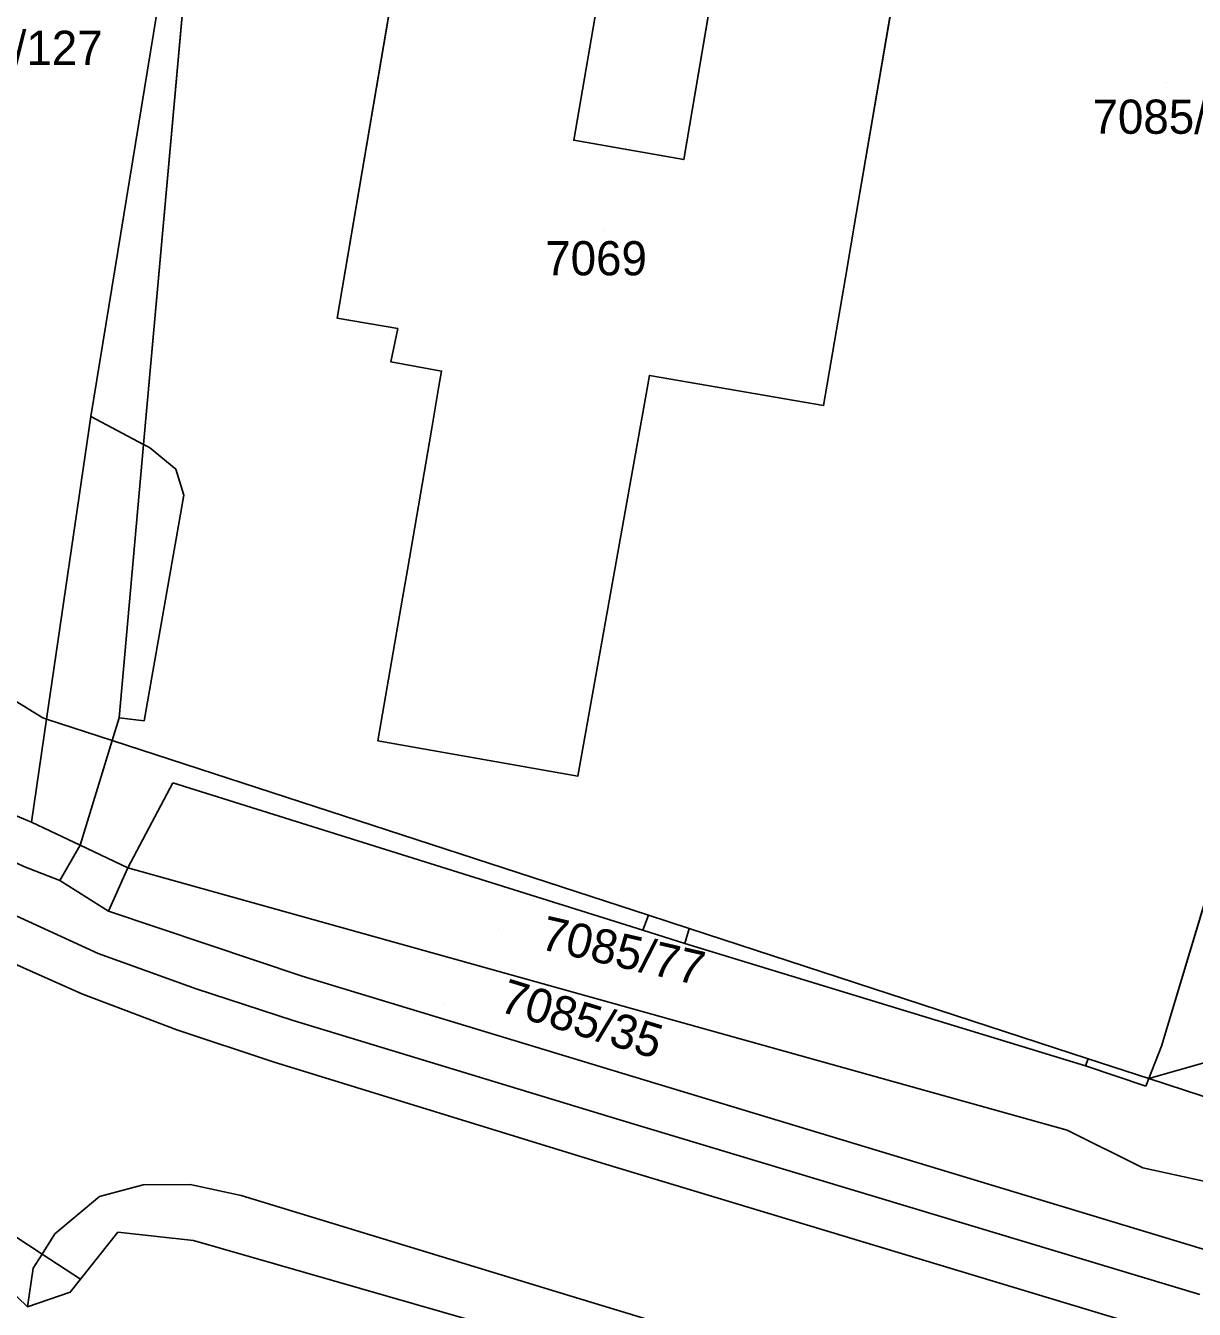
# Model space of a CAD drawing. Extents: x -266199 to -261993, y -1239047 to -1235108.
# Drawn here: x -263664.7 to -263596.4, y -1236922.3 to -1236847.2 of the extents above; entities that cross this region are included whole.
import ezdxf

# ---------------------------------------------------------------- set-up
doc = ezdxf.new("R2010")
doc.units = 0
for name, color, linetype in [('body_kn', 7, 'Continuous'), ('kladpar_druhypozemkov', 7, 'Continuous'), ('kladpar_hranice', 7, 'Continuous'), ('kladpar_parcelnecisla', 7, 'Continuous'), ('kladpar_plochy', 7, 'Continuous'), ('zappar_hrandruhpozemk', 7, 'Continuous'), ('zuob_linie', 7, 'Continuous'), ('zuob_plochy', 7, 'Continuous')]:
    doc.layers.add(name, color=color, linetype=linetype)

msp = doc.modelspace()

# ---------------------------------------------------------------- linework, layer by layer
at = {"layer": 'body_kn'}
for p, q in [((-263632.67, -1236853.87), (-263632.67, -1236853.87)), ((-263626.23, -1236855), (-263626.23, -1236855)), ((-263616.14, -1236858.2), (-263616.14, -1236858.2)), ((-263616.77, -1236861.9), (-263616.77, -1236861.9)), ((-263646.51, -1236864.27), (-263646.51, -1236864.27)), ((-263642.96, -1236864.89), (-263642.96, -1236864.89)), ((-263643.36, -1236866.84), (-263643.36, -1236866.84)), ((-263640.4, -1236867.37), (-263640.4, -1236867.37)), ((-263628.24, -1236867.63), (-263628.24, -1236867.63)), ((-263640.55, -1236868.26), (-263640.55, -1236868.26)), ((-263618.05, -1236869.39), (-263618.05, -1236869.39)), ((-263660.92, -1236870.02), (-263660.92, -1236870.02)), ((-263660.92, -1236870.02), (-263660.92, -1236870.02)), ((-263640.99, -1236870.82), (-263640.99, -1236870.82)), ((-263657.83, -1236871.66), (-263657.83, -1236871.66)), ((-263657.49, -1236871.84), (-263657.49, -1236871.84)), ((-263655.94, -1236873.12), (-263655.94, -1236873.12)), ((-263655.48, -1236874.64), (-263655.48, -1236874.64)), ((-263642.4, -1236879), (-263642.4, -1236879)), ((-263642.68, -1236880.66), (-263642.68, -1236880.66)), ((-263663.72, -1236887.66), (-263663.72, -1236887.66)), ((-263659.27, -1236887.66), (-263659.27, -1236887.66)), ((-263659.27, -1236887.66), (-263659.27, -1236887.66)), ((-263663.51, -1236887.73), (-263663.51, -1236887.73)), ((-263663.51, -1236887.73), (-263663.51, -1236887.73)), ((-263657.79, -1236887.84), (-263657.79, -1236887.84)), ((-263659.67, -1236888.98), (-263659.67, -1236888.98)), ((-263659.67, -1236888.98), (-263659.67, -1236888.98)), ((-263644.12, -1236889.01), (-263644.12, -1236889.01)), ((-263644.12, -1236889.01), (-263644.12, -1236889.01)), ((-263656.13, -1236891.47), (-263656.13, -1236891.47)), ((-263632.42, -1236891.07), (-263632.42, -1236891.07)), ((-263664.39, -1236893.76), (-263664.39, -1236893.76)), ((-263661.55, -1236895.1), (-263661.55, -1236895.1)), ((-263661.55, -1236895.1), (-263661.55, -1236895.1)), ((-263658.75, -1236896.43), (-263658.75, -1236896.43)), ((-263662.73, -1236897.18), (-263662.73, -1236897.18)), ((-263659.89, -1236898.97), (-263659.89, -1236898.97)), ((-263659.89, -1236898.97), (-263659.89, -1236898.97)), ((-263628.3, -1236899.21), (-263628.3, -1236899.21)), ((-263628.3, -1236899.21), (-263628.3, -1236899.21)), ((-263628.63, -1236900.09), (-263628.63, -1236900.09)), ((-263628.63, -1236900.09), (-263628.63, -1236900.09)), ((-263625.92, -1236899.99), (-263625.92, -1236899.99)), ((-263625.92, -1236899.99), (-263625.92, -1236899.99)), ((-263654.07, -1236900.91), (-263654.07, -1236900.91)), ((-263626.17, -1236900.86), (-263626.17, -1236900.86)), ((-263626.17, -1236900.86), (-263626.17, -1236900.86)), ((-263660.49, -1236901.44), (-263660.49, -1236901.44)), ((-263648.55, -1236902.77), (-263648.55, -1236902.77)), ((-263661.44, -1236903.81), (-263661.44, -1236903.81)), ((-263654.75, -1236903.52), (-263654.75, -1236903.52)), ((-263649.09, -1236905.37), (-263649.09, -1236905.37)), ((-263655.88, -1236905.92), (-263655.88, -1236905.92)), ((-263598.28, -1236906.87), (-263598.28, -1236906.87)), ((-263650.25, -1236907.78), (-263650.25, -1236907.78)), ((-263602.57, -1236907.6), (-263602.57, -1236907.6)), ((-263602.57, -1236907.6), (-263602.57, -1236907.6)), ((-263629.21, -1236908.64), (-263629.21, -1236908.64)), ((-263602.72, -1236908.02), (-263602.72, -1236908.02)), ((-263602.72, -1236908.02), (-263602.72, -1236908.02)), ((-263599.19, -1236909.2), (-263599.19, -1236909.2)), ((-263599.02, -1236908.76), (-263599.02, -1236908.76)), ((-263599.02, -1236908.76), (-263599.02, -1236908.76)), ((-263630.16, -1236911.12), (-263630.16, -1236911.12)), ((-263603.79, -1236911.79), (-263603.79, -1236911.79)), ((-263631.01, -1236913.72), (-263631.01, -1236913.72)), ((-263599.38, -1236913.98), (-263599.38, -1236913.98)), ((-263657.85, -1236914.98), (-263657.85, -1236914.98)), ((-263655.11, -1236914.96), (-263655.11, -1236914.96)), ((-263660.41, -1236915.67), (-263660.41, -1236915.67)), ((-263652.12, -1236915.61), (-263652.12, -1236915.61)), ((-263659.33, -1236917.75), (-263659.33, -1236917.75)), ((-263663.02, -1236917.85), (-263663.02, -1236917.85)), ((-263654.92, -1236918.23), (-263654.92, -1236918.23)), ((-263663.77, -1236919.03), (-263663.77, -1236919.03)), ((-263664.3, -1236919.86), (-263664.3, -1236919.86)), ((-263661.52, -1236920.5), (-263661.52, -1236920.5)), ((-263661.52, -1236920.5), (-263661.52, -1236920.5)), ((-263662.12, -1236921.26), (-263662.12, -1236921.26)), ((-263632.76, -1236921.51), (-263632.76, -1236921.51)), ((-263664.62, -1236922.11), (-263664.62, -1236922.11)), ((-263664.62, -1236922.11), (-263664.62, -1236922.11))]:
    msp.add_line(p, q, dxfattribs=at)
at = {"layer": 'kladpar_druhypozemkov'}
for p, q in [((-263597.97, -1236850.5), (-263597.97, -1236850.5)), ((-263630.95, -1236859.17), (-263630.95, -1236859.17)), ((-263637.06, -1236900.02), (-263637.06, -1236900.02)), ((-263640.21, -1236904.41), (-263640.21, -1236904.41))]:
    msp.add_line(p, q, dxfattribs=at)
at = {"layer": 'kladpar_hranice'}
for points in [[(-263644.25, -1236792.2), (-263643.55, -1236801.17), (-263651.4, -1236804.98), (-263653.36, -1236823.82), (-263653.7, -1236825.82), (-263657.83, -1236871.66), (-263659.27, -1236887.66), (-263659.67, -1236888.98)], [(-263659.67, -1236888.98), (-263659.27, -1236887.66), (-263657.83, -1236871.66), (-263653.7, -1236825.82), (-263653.36, -1236823.82), (-263651.4, -1236804.98), (-263643.55, -1236801.17)], [(-263643.55, -1236801.17), (-263643.41, -1236803.03), (-263638.37, -1236803.18), (-263613.97, -1236803.91), (-263614.03, -1236806.55), (-263585.37, -1236807.14), (-263579.23, -1236807.27), (-263579.09, -1236804.96), (-263566.69, -1236804.81), (-263568.91, -1236807.57), (-263570.28, -1236812.26), (-263570.64, -1236814.85), (-263598.28, -1236906.87), (-263599.02, -1236908.76)], [(-263599.02, -1236908.76), (-263598.28, -1236906.87), (-263570.64, -1236814.85), (-263570.28, -1236812.26), (-263568.91, -1236807.57), (-263566.69, -1236804.81), (-263553.7, -1236804.94), (-263548.78, -1236805.34), (-263526.3, -1236807.18), (-263518.66, -1236807.81), (-263509.65, -1236808.55)], [(-263622.19, -1236831.21), (-263626.23, -1236855), (-263632.67, -1236853.87), (-263629.6, -1236836.05)], [(-263629.6, -1236836.05), (-263632.67, -1236853.87), (-263626.23, -1236855), (-263622.19, -1236831.21)], [(-263642.68, -1236880.66), (-263644.12, -1236889.01), (-263632.42, -1236891.07), (-263628.24, -1236867.63), (-263618.05, -1236869.39), (-263616.77, -1236861.9), (-263616.14, -1236858.2), (-263611.83, -1236832.93)], [(-263611.83, -1236832.93), (-263616.14, -1236858.2), (-263616.77, -1236861.9), (-263618.05, -1236869.39), (-263628.24, -1236867.63), (-263632.42, -1236891.07), (-263644.12, -1236889.01)], [(-263641.34, -1236833.95), (-263646.51, -1236864.27), (-263642.96, -1236864.89), (-263643.36, -1236866.84), (-263640.4, -1236867.37), (-263640.55, -1236868.26), (-263640.99, -1236870.82), (-263642.4, -1236879), (-263642.68, -1236880.66)], [(-263644.12, -1236889.01), (-263642.68, -1236880.66), (-263642.4, -1236879), (-263640.99, -1236870.82), (-263640.55, -1236868.26), (-263640.4, -1236867.37), (-263643.36, -1236866.84), (-263642.96, -1236864.89), (-263646.51, -1236864.27), (-263641.34, -1236833.95)], [(-263737.21, -1236847.24), (-263728.66, -1236852.26), (-263724.24, -1236852.11), (-263723.45, -1236852.13), (-263724.23, -1236854.5), (-263697.93, -1236874.68), (-263690.23, -1236880.72), (-263684.19, -1236885.23), (-263677.59, -1236889.83), (-263671.4, -1236893.24), (-263664.84, -1236896.35), (-263662.73, -1236897.18), (-263659.89, -1236898.97), (-263654.07, -1236900.91), (-263648.55, -1236902.77), (-263629.21, -1236908.64), (-263595.25, -1236918.92), (-263562.06, -1236928.83), (-263554.45, -1236930.8), (-263544.76, -1236933.48), (-263538.17, -1236935.17), (-263533.8, -1236935.53), (-263530.81, -1236934.92), (-263526.53, -1236931.83)], [(-263724.23, -1236854.5), (-263723.45, -1236852.13), (-263718.46, -1236856.19), (-263688.65, -1236880.45), (-263667.08, -1236892.65), (-263664.39, -1236893.76), (-263661.55, -1236895.1), (-263658.75, -1236896.43), (-263603.79, -1236911.79), (-263599.38, -1236913.98), (-263570.2, -1236920.36), (-263567.73, -1236922.05), (-263548.45, -1236926.82), (-263544.92, -1236925.99)], [(-263526.53, -1236931.83), (-263530.81, -1236934.92), (-263533.8, -1236935.53), (-263538.17, -1236935.17), (-263544.76, -1236933.48), (-263554.45, -1236930.8), (-263562.06, -1236928.83), (-263595.25, -1236918.92), (-263629.21, -1236908.64), (-263648.55, -1236902.77), (-263654.07, -1236900.91), (-263659.89, -1236898.97), (-263662.73, -1236897.18), (-263664.84, -1236896.35), (-263671.4, -1236893.24), (-263677.59, -1236889.83), (-263684.19, -1236885.23), (-263690.23, -1236880.72), (-263697.93, -1236874.68), (-263724.23, -1236854.5)], [(-263733.47, -1236855.86), (-263713.69, -1236874.8), (-263696.81, -1236886.55), (-263676.82, -1236905.09), (-263676.36, -1236905.67), (-263672.63, -1236910.36), (-263669.15, -1236914.74), (-263667.89, -1236916.33), (-263663.77, -1236919.03), (-263661.52, -1236920.5)], [(-263661.52, -1236920.5), (-263663.77, -1236919.03), (-263667.89, -1236916.33), (-263669.15, -1236914.74), (-263672.63, -1236910.36), (-263676.36, -1236905.67), (-263676.82, -1236905.09), (-263696.81, -1236886.55), (-263713.69, -1236874.8), (-263733.47, -1236855.86)], [(-263659.67, -1236888.98), (-263661.55, -1236895.1), (-263664.39, -1236893.76), (-263667.08, -1236892.65), (-263688.65, -1236880.45), (-263718.46, -1236856.19)], [(-263706.58, -1236856.95), (-263706.57, -1236857.79), (-263706.53, -1236861.38), (-263683.08, -1236875.77), (-263682.22, -1236876.3), (-263680.13, -1236877.59), (-263675.03, -1236880.72), (-263673, -1236881.96), (-263663.72, -1236887.66), (-263663.51, -1236887.73), (-263659.67, -1236888.98)], [(-263659.67, -1236888.98), (-263663.51, -1236887.73), (-263663.72, -1236887.66), (-263673, -1236881.96), (-263675.03, -1236880.72), (-263680.13, -1236877.59), (-263682.22, -1236876.3), (-263683.08, -1236875.77), (-263706.53, -1236861.38), (-263706.57, -1236857.79), (-263706.58, -1236856.95)], [(-263661.52, -1236920.5), (-263662.12, -1236921.26), (-263664.62, -1236922.11), (-263671.17, -1236915.79), (-263672.5, -1236915.8), (-263674.03, -1236914.82), (-263676.68, -1236911.73), (-263678.51, -1236907.35), (-263684.57, -1236903.94), (-263685.53, -1236903.5), (-263696.74, -1236898.33), (-263700.51, -1236896.79), (-263718.6, -1236882.98), (-263723.65, -1236877.89), (-263725.55, -1236876.13)], [(-263544.92, -1236925.99), (-263548.45, -1236926.82), (-263567.73, -1236922.05), (-263570.2, -1236920.36), (-263599.38, -1236913.98), (-263603.79, -1236911.79), (-263658.75, -1236896.43), (-263661.55, -1236895.1), (-263659.67, -1236888.98)], [(-263599.02, -1236908.76), (-263602.57, -1236907.6), (-263625.92, -1236899.99), (-263628.3, -1236899.21), (-263659.67, -1236888.98)], [(-263659.67, -1236888.98), (-263628.3, -1236899.21), (-263625.92, -1236899.99), (-263602.57, -1236907.6), (-263599.02, -1236908.76), (-263594.85, -1236910.12), (-263584.48, -1236913.42), (-263544.92, -1236925.99)], [(-263520.64, -1236923.49), (-263518.7, -1236920.21), (-263516.4, -1236911.92), (-263515.05, -1236902.26), (-263517.52, -1236927.1), (-263519.86, -1236969.84), (-263523.24, -1236974.84), (-263525.44, -1236967.7), (-263525.85, -1236967.05), (-263527.45, -1236964.54), (-263527.7, -1236964.14), (-263533.48, -1236958.28), (-263539.31, -1236955.76), (-263556.44, -1236948.35), (-263567.43, -1236943.68), (-263598.26, -1236934.52), (-263654.92, -1236918.23), (-263659.33, -1236917.75), (-263661.52, -1236920.5)], [(-263526.53, -1236931.83), (-263544.92, -1236925.99), (-263584.48, -1236913.42), (-263594.85, -1236910.12), (-263599.02, -1236908.76), (-263582.4, -1236904.03)]]:
    msp.add_lwpolyline(points, dxfattribs=at)
at = {"layer": 'kladpar_plochy'}
for p, q in [((-263570.64, -1236814.85), (-263598.28, -1236906.87)), ((-263598.28, -1236906.87), (-263570.64, -1236814.85)), ((-263657.83, -1236871.66), (-263653.7, -1236825.82)), ((-263622.19, -1236831.21), (-263626.23, -1236855)), ((-263616.14, -1236858.2), (-263611.83, -1236832.93)), ((-263641.34, -1236833.95), (-263646.51, -1236864.27)), ((-263632.67, -1236853.87), (-263629.6, -1236836.05)), ((-263626.23, -1236855), (-263632.67, -1236853.87)), ((-263616.77, -1236861.9), (-263616.14, -1236858.2)), ((-263618.05, -1236869.39), (-263616.77, -1236861.9)), ((-263646.51, -1236864.27), (-263642.96, -1236864.89)), ((-263642.96, -1236864.89), (-263643.36, -1236866.84)), ((-263643.36, -1236866.84), (-263640.4, -1236867.37)), ((-263640.4, -1236867.37), (-263640.55, -1236868.26)), ((-263632.42, -1236891.07), (-263628.24, -1236867.63)), ((-263628.24, -1236867.63), (-263618.05, -1236869.39)), ((-263640.55, -1236868.26), (-263640.99, -1236870.82)), ((-263640.99, -1236870.82), (-263642.4, -1236879)), ((-263659.27, -1236887.66), (-263657.83, -1236871.66)), ((-263642.4, -1236879), (-263642.68, -1236880.66)), ((-263642.68, -1236880.66), (-263644.12, -1236889.01)), ((-263659.67, -1236888.98), (-263659.27, -1236887.66)), ((-263628.3, -1236899.21), (-263659.67, -1236888.98)), ((-263644.12, -1236889.01), (-263632.42, -1236891.07)), ((-263625.92, -1236899.99), (-263628.3, -1236899.21)), ((-263602.57, -1236907.6), (-263625.92, -1236899.99)), ((-263598.28, -1236906.87), (-263599.02, -1236908.76)), ((-263599.02, -1236908.76), (-263598.28, -1236906.87)), ((-263599.02, -1236908.76), (-263602.57, -1236907.6)), ((-263594.85, -1236910.12), (-263599.02, -1236908.76))]:
    msp.add_line(p, q, dxfattribs=at)
for points in [[(-263653.7, -1236825.82), (-263657.83, -1236871.66), (-263659.27, -1236887.66), (-263659.67, -1236888.98), (-263663.51, -1236887.73), (-263663.72, -1236887.66), (-263673, -1236881.96), (-263675.03, -1236880.72), (-263680.13, -1236877.59), (-263682.22, -1236876.3), (-263683.08, -1236875.77), (-263706.53, -1236861.38), (-263706.57, -1236857.79), (-263706.58, -1236856.95), (-263704.55, -1236858.41), (-263682.17, -1236874.56), (-263680.06, -1236874.56), (-263674.92, -1236874.56), (-263673.25, -1236874.56), (-263673.08, -1236857.59), (-263672.54, -1236823.65)], [(-263629.6, -1236836.05), (-263632.67, -1236853.87), (-263626.23, -1236855), (-263622.19, -1236831.21)], [(-263611.83, -1236832.93), (-263616.14, -1236858.2), (-263616.77, -1236861.9), (-263618.05, -1236869.39), (-263628.24, -1236867.63), (-263632.42, -1236891.07), (-263644.12, -1236889.01), (-263642.68, -1236880.66), (-263642.4, -1236879), (-263640.99, -1236870.82), (-263640.55, -1236868.26), (-263640.4, -1236867.37), (-263643.36, -1236866.84), (-263642.96, -1236864.89), (-263646.51, -1236864.27), (-263641.34, -1236833.95)], [(-263737.21, -1236847.24), (-263728.66, -1236852.26), (-263724.24, -1236852.11), (-263723.45, -1236852.13), (-263724.23, -1236854.5), (-263697.93, -1236874.68), (-263690.23, -1236880.72), (-263684.19, -1236885.23), (-263677.59, -1236889.83), (-263671.4, -1236893.24), (-263664.84, -1236896.35), (-263662.73, -1236897.18), (-263659.89, -1236898.97), (-263654.07, -1236900.91), (-263648.55, -1236902.77), (-263629.21, -1236908.64), (-263595.25, -1236918.92), (-263562.06, -1236928.83)], [(-263595.25, -1236918.92), (-263629.21, -1236908.64), (-263648.55, -1236902.77), (-263654.07, -1236900.91), (-263659.89, -1236898.97), (-263662.73, -1236897.18), (-263664.84, -1236896.35), (-263671.4, -1236893.24), (-263677.59, -1236889.83), (-263684.19, -1236885.23), (-263690.23, -1236880.72), (-263697.93, -1236874.68), (-263724.23, -1236854.5), (-263723.45, -1236852.13), (-263718.46, -1236856.19), (-263688.65, -1236880.45), (-263667.08, -1236892.65), (-263664.39, -1236893.76), (-263661.55, -1236895.1), (-263658.75, -1236896.43), (-263603.79, -1236911.79), (-263599.38, -1236913.98), (-263570.2, -1236920.36)], [(-263598.26, -1236934.52), (-263654.92, -1236918.23), (-263659.33, -1236917.75), (-263661.52, -1236920.5), (-263663.77, -1236919.03), (-263667.89, -1236916.33), (-263669.15, -1236914.74), (-263672.63, -1236910.36), (-263676.36, -1236905.67), (-263676.82, -1236905.09), (-263696.81, -1236886.55), (-263713.69, -1236874.8), (-263733.47, -1236855.86)], [(-263667.89, -1236916.33), (-263663.77, -1236919.03), (-263661.52, -1236920.5), (-263662.12, -1236921.26), (-263664.62, -1236922.11), (-263671.17, -1236915.79)]]:
    msp.add_lwpolyline(points, dxfattribs=at)
for points in [[(-263718.46, -1236856.19), (-263718.32, -1236848.48), (-263706.58, -1236856.95), (-263706.57, -1236857.79), (-263706.53, -1236861.38), (-263683.08, -1236875.77), (-263682.22, -1236876.3), (-263680.13, -1236877.59), (-263675.03, -1236880.72), (-263673, -1236881.96), (-263663.72, -1236887.66), (-263663.51, -1236887.73), (-263659.67, -1236888.98), (-263661.55, -1236895.1), (-263664.39, -1236893.76), (-263667.08, -1236892.65), (-263688.65, -1236880.45)], [(-263659.67, -1236888.98), (-263628.3, -1236899.21), (-263625.92, -1236899.99), (-263602.57, -1236907.6), (-263599.02, -1236908.76), (-263594.85, -1236910.12), (-263584.48, -1236913.42), (-263544.92, -1236925.99), (-263548.45, -1236926.82), (-263567.73, -1236922.05), (-263570.2, -1236920.36), (-263599.38, -1236913.98), (-263603.79, -1236911.79), (-263658.75, -1236896.43), (-263661.55, -1236895.1)]]:
    msp.add_lwpolyline(points, close=True, dxfattribs=at)
at = {"layer": 'zappar_hrandruhpozemk'}
for p, q in [((-263653.7, -1236825.82), (-263660.92, -1236870.02)), ((-263663.51, -1236887.73), (-263660.92, -1236870.02)), ((-263660.92, -1236870.02), (-263657.83, -1236871.66)), ((-263657.79, -1236887.84), (-263655.48, -1236874.64)), ((-263659.67, -1236888.98), (-263659.27, -1236887.66)), ((-263659.27, -1236887.66), (-263657.79, -1236887.84)), ((-263663.51, -1236887.73), (-263664.39, -1236893.76)), ((-263656.13, -1236891.47), (-263658.75, -1236896.43)), ((-263628.63, -1236900.09), (-263656.13, -1236891.47)), ((-263661.55, -1236895.1), (-263662.73, -1236897.18)), ((-263659.89, -1236898.97), (-263658.75, -1236896.43)), ((-263666, -1236898.91), (-263660.49, -1236901.44)), ((-263628.3, -1236899.21), (-263628.63, -1236900.09)), ((-263626.17, -1236900.86), (-263628.63, -1236900.09)), ((-263625.92, -1236899.99), (-263626.17, -1236900.86)), ((-263602.72, -1236908.02), (-263626.17, -1236900.86)), ((-263602.57, -1236907.6), (-263602.72, -1236908.02)), ((-263599.19, -1236909.2), (-263602.72, -1236908.02)), ((-263599.02, -1236908.76), (-263599.19, -1236909.2)), ((-263596.68, -1236924.06), (-263631.01, -1236913.72)), ((-263652.12, -1236915.61), (-263655.11, -1236914.96)), ((-263632.76, -1236921.51), (-263652.12, -1236915.61)), ((-263664.3, -1236919.86), (-263663.77, -1236919.03)), ((-263664.62, -1236922.11), (-263664.3, -1236919.86)), ((-263599.88, -1236931.46), (-263632.76, -1236921.51))]:
    msp.add_line(p, q, dxfattribs=at)
for points in [[(-263655.48, -1236874.64), (-263655.94, -1236873.12), (-263657.49, -1236871.84), (-263657.83, -1236871.66)], [(-263631.01, -1236913.72), (-263650.25, -1236907.78), (-263655.88, -1236905.92), (-263661.44, -1236903.81), (-263668.28, -1236900.76), (-263674.36, -1236897.75), (-263681.64, -1236893.53)], [(-263660.49, -1236901.44), (-263654.75, -1236903.52), (-263649.09, -1236905.37), (-263630.16, -1236911.12), (-263596.04, -1236921.39)], [(-263655.11, -1236914.96), (-263657.85, -1236914.98), (-263660.41, -1236915.67), (-263663.02, -1236917.85), (-263663.77, -1236919.03)]]:
    msp.add_lwpolyline(points, dxfattribs=at)
at = {"layer": 'zuob_linie'}
msp.add_lwpolyline([(-263598.26, -1236934.52), (-263654.92, -1236918.23), (-263659.33, -1236917.75), (-263661.52, -1236920.5), (-263662.12, -1236921.26), (-263664.62, -1236922.11), (-263671.17, -1236915.79), (-263672.5, -1236915.8), (-263674.03, -1236914.82), (-263676.68, -1236911.73), (-263678.51, -1236907.35), (-263684.57, -1236903.94), (-263685.53, -1236903.5), (-263696.74, -1236898.33), (-263700.51, -1236896.79), (-263718.6, -1236882.98), (-263723.65, -1236877.89), (-263725.55, -1236876.13), (-263727.98, -1236873.89), (-263730.31, -1236871.57), (-263733.77, -1236869.03)], dxfattribs=at)
at = {"layer": 'zuob_plochy'}
msp.add_lwpolyline([(-263598.26, -1236934.52), (-263654.92, -1236918.23), (-263659.33, -1236917.75), (-263661.52, -1236920.5), (-263662.12, -1236921.26), (-263664.62, -1236922.11), (-263671.17, -1236915.79), (-263672.5, -1236915.8), (-263674.03, -1236914.82), (-263676.68, -1236911.73), (-263678.51, -1236907.35), (-263684.57, -1236903.94), (-263685.53, -1236903.5), (-263696.74, -1236898.33), (-263700.51, -1236896.79), (-263718.6, -1236882.98), (-263723.65, -1236877.89), (-263725.55, -1236876.13), (-263727.98, -1236873.89), (-263730.31, -1236871.57), (-263733.77, -1236869.03)], dxfattribs=at)

# ---------------------------------------------------------------- texts
at = {"layer": 'kladpar_parcelnecisla'}
for s, p in [('7085/127', (-263671.383, -1236849.46)), ('7085/2', (-263602.317, -1236853.49)), ('7069', (-263634.334, -1236861.77))]:
    msp.add_text(s, height=2, dxfattribs=at).set_placement(p)
for s, rotation, p in [('7085/77', 347, (-263634.708, -1236901.166)), ('7085/35', 343, (-263637.104, -1236904.804))]:
    msp.add_text(s, height=2, rotation=rotation, dxfattribs=at).set_placement(p)

doc.saveas('drawing.dxf')
